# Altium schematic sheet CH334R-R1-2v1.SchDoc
size 209 x 148 mm; PageSetup: Record=PageOptions¦CenterHorizontal=True¦CenterVertical=True¦PrintScale=0.88¦XCorrection=1.00¦YCorrection=1.00¦PrintKind=1¦BorderSize=5000000¦LeftOffset=0¦BottomOffset=0¦Orientation=2¦PaperLength=1000¦PaperWidth=1000¦Scale=100¦PaperSource=7¦PrintQuality=-4¦MediaType=1¦DitherType=10¦PaperKind=16 开 195x270¦PrintScaleMode=1
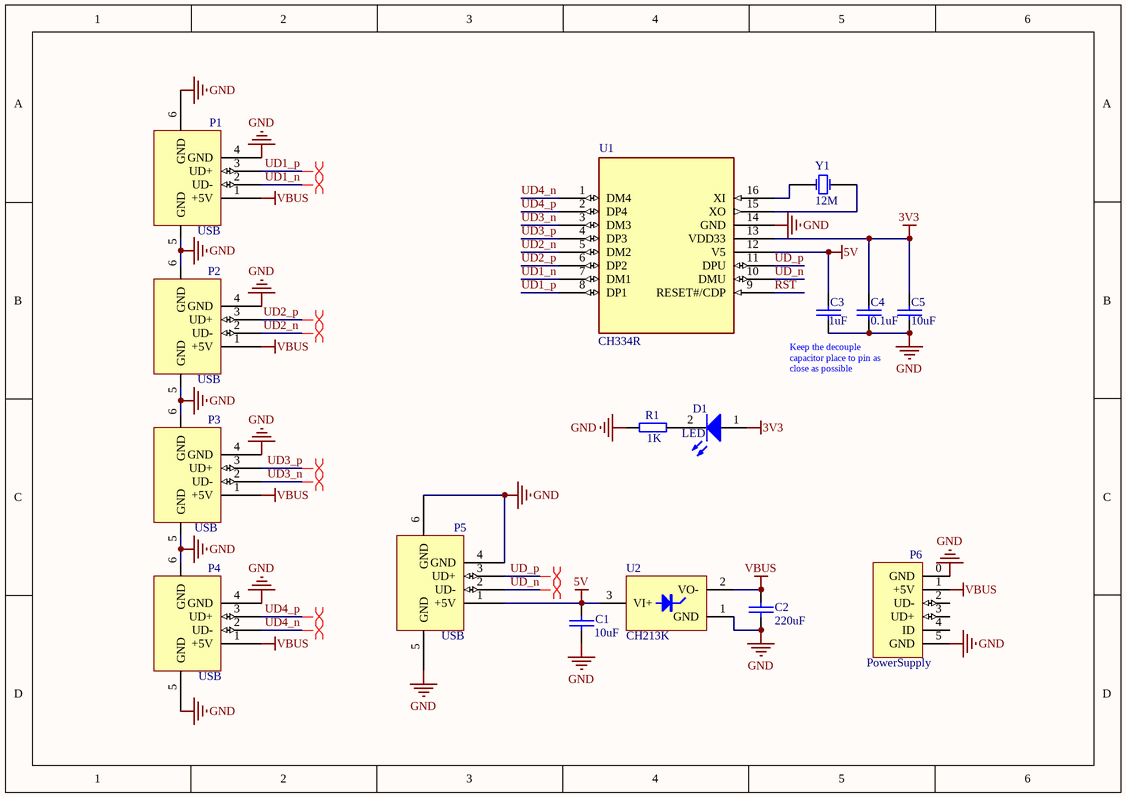
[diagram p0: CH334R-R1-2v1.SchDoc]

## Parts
C1  10uF  [0603_C]
C2  220uF  [CD0.1]
C3  1uF  [0603_C]
C4  0.1uF  [0603_C]
C5  10uF  [0603_C]
D1  LED  [0603+]
P1  USB  [USB2.0-A-F-TH_4P-V_13.7mm]
P2  USB  [USB2.0-A-F-TH_4P-V_13.7mm]
P3  USB  [USB2.0-A-F-TH_4P-V_13.7mm]
P4  USB  [USBAF]
P5  USB  [USBAF]
P6  PowerSupply  [USBMICROB-02-GXPX-A1T2]
R1  1K  [0603_R]
U1  CH334R  [QSOP16]
U2  CH213K  [SOT-23-3]
Y1  12M  [XT_AT49]

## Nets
3V3: C4.1 C5.1 D1.1(A) U1.13(VDD33)
5V: C1.1 C3.1 P5.1(+5V) U1.12(V5) U2.3(VI+)
GND: C1.2 C2.2 C3.2 C4.2 C5.2 P1.4(GND) P1.5(GND) P1.6(GND) P2.4(GND) P2.5(GND) P2.6(GND) P3.4(GND) P3.5(GND) P3.6(GND) P4.4(GND) P4.5(GND) P4.6(GND) P5.4(GND) P5.5(GND) P5.6(GND) P6.0(GND) P6.5(GND) R1.1 U1.14(GND) U2.1(GND)
VBUS: C2.1 P1.1(+5V) P2.1(+5V) P3.1(+5V) P4.1(+5V) P6.1(+5V) U2.2(VO-)
RST: U1.9(RESET#/CDP)
UD1_n: P1.2(UD-) U1.7(DM1)
UD1_p: P1.3(UD+) U1.8(DP1)
UD2_n: P2.2(UD-) U1.5(DM2)
UD2_p: P2.3(UD+) U1.6(DP2)
UD3_n: P3.2(UD-) U1.3(DM3)
UD3_p: P3.3(UD+) U1.4(DP3)
UD4_n: P4.2(UD-) U1.1(DM4)
UD4_p: P4.3(UD+) U1.2(DP4)
UD_n: P5.2(UD-) U1.10(DMU)
UD_p: P5.3(UD+) U1.11(DPU)
NetD1_2: D1.2(K) R1.2
NetU1_15: U1.15(XO) Y1.2(OSC2)
NetU1_16: U1.16(XI) Y1.1(OSC1)

Not connected (* = marked no-connect by the designer): P6 2(UD-) 3(UD+) 4(ID)

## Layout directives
differential pair: UD1_n, UD1_p, UD2_n, UD2_p, UD3_n, UD3_p, UD4_n, UD4_p, UD_n, UD_p

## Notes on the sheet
- Keep the decouple capacitor place to pin as close as possible

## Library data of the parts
C1-C5 = CAP: Capacitor
D1 = LED: Typical INFRARED GaAs LED
P1-P5 = USB: USB Port
P6 = MicroUSB: MicroUSB Port
R1 = RES
U1 = CH334R: 4 ports High-Speed USB MTT Hub
U2 = CH213K: Ideal Diode 5V*1A
Y1 = XTAL: Crystal Oscillator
